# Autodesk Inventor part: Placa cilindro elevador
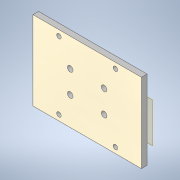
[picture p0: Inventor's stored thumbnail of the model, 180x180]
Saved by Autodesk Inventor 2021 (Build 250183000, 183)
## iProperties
Created: 2021-02
Part Number: Placa cilindro elevador
Material: Genérico
Document SubType Name: Modeling
Designer: ATOUZA
Density: 1 g/cm^3
Appearance: Valor por defecto
Author: ATOUZA
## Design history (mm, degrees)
node "Plano de trabajo1"
sketch "Boceto1"
  geometry: L1 (-48, -16)-(-48, 16) reference; L2 (48, -16)-(-48, -16) reference; L3 (48, 16)-(48, -16) reference; L4 (-48, 16)-(48, 16) reference; L5 (0, 16)-(0, -16); L6 (48, -35)-(-48, -35); L7 (-48, -35)-(-48, 35); L8 (-48, 35)-(48, 35); L9 (48, 35)-(48, -35); L10 (48, -35)-(-48, 35); L11 (-48, -35)-(48, 35); L12 (-48, 0)-(0, 0); L13 (-25, 0)-(-25, 35); C1 r 2.5 at (15, 10) reference; C2 r 2.5 at (15, -10) reference; C3 r 2.5 at (-15, 10) reference; C4 r 2.5 at (-15, -10) reference; C5 r 5 at (25, 0) reference; C6 r 5 at (-25, 0) reference; C7 r 2.5 at (-15, 10); C8 r 2.5 at (15, 10); C9 r 2.5 at (15, -10); C10 r 2.5 at (-15, -10); C11 r 2 at (-25, 30); C12 r 2 at (-25, -30); C13 r 2 at (25, -30); C14 r 2 at (25, 30)
  constraints: 18 end point, 8 centre point, 5 midpoint, 4 coincident, 4 concentric, 3 perpendicular, 3 symmetric about line, 2 parallel, 2 point on line, 1 horizontal, 3 other
  dimensions: "d0" = 96 distance of L7.end L8.end; "d1" = 70 distance of L6.end L7.end; "d2" = 4 diameter of C11; "d3" = 5 distance from line of L8 C11.centre
extrude "Extrusión1" new body sketch "Boceto1" distance "d4" = 5; taper "d5" = 0 deg
node "Sólido1"
node "Referencia1"
